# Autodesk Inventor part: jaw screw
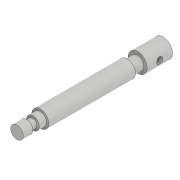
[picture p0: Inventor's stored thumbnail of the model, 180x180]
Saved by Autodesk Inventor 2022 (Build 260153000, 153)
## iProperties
Created: 2016-03
Part Number: jaw screw
Material: Generic
Document SubType Name: Modeling
Designer: Sandeep
Density: 1 g/cm^3
Appearance: Default
Mass: 25.5852 g
Surface Area: 75.8462 cm^2
Volume: 25.5852 cm^3
Author: Sandeep
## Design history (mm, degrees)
sketch "Sketch1"
  geometry: L1 (0, -138)-(-6, -138); L2 (-6, -116)-(-6, -116); L3 (-6, -116)-(-8, -116); L4 (-8, -116)-(-8, -34); L5 (-8, -34)-(-6, -34); L6 (-6, -34)-(-6, -24); L7 (-6, -24)-(-9, -24); L8 (-9, -24)-(-9, 0); L9 (-9, 0)-(0, 0); L10 (0, 0)-(0, -138); L11 (0, 0)-(0, 14.581); L12 (-6, -116)-(-6, -123); L13 (-6, -123)-(-4, -123); L14 (-4, -123)-(-4, -129); L15 (-4, -129)-(-6, -129); L16 (-6, -129)-(-6, -138); 1 other entity
  constraints: 32 end point, 10 perpendicular, 3 point on line, 3 vertical, 1 coincident, 1 horizontal, 2 other
  dimensions: "d0" = 18 diameter of L8 L11; "d1" = 12 diameter of L6 L11; "d3" = 24 distance of L7.end L8.end; "d4" = 10 distance of L5.end L6.end; "d5" = 82 distance of L3.end L4.end; "d6" = 138 distance between parallel lines of L1 L9; "d8" = 16 diameter of L4 L11; "d10" = 6 distance of L13.end L14.end; "d11" = 9 distance of L15.end L1.end; "d12" = 8 diameter of L14 L11
revolve "Revolution1" sketch "Sketch1" stored, may be unused: angle "d9" = 90 deg
sketch "Sketch2"
  geometry: L1 (0, -9)-(0, 9) reference; L2 (0, 0)-(-20.975, 0); C1 r 3 at (-12, 0)
  constraints: 2 end point, 1 centre point, 1 horizontal, 1 point on line
  dimensions: "d13" = 6 diameter of C1; "d14" = 12 distance from line of L1 C1.centre
extrude "Extrusion1" cut sketch "Sketch2" distance "d15" = 25; taper "d16" = 0 deg
body "Solid1"
